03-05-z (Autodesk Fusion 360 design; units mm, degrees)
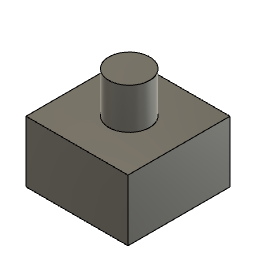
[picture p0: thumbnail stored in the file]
box_primitive "直方体プリミティブ" DistanceX 50 DistanceY 50 DistanceZ 30 OffsetDistanceX 0 OffsetDistanceY 0
cylinder_primitive "円柱プリミティブ" Height 20 Diameter 20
